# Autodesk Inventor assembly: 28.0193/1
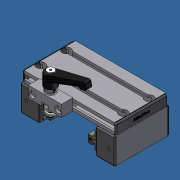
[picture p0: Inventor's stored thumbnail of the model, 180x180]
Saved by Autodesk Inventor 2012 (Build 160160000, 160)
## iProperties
Created: 2007-06
Part Number: 28.0193/1
Document SubType Name: Assembly
Designer: Andy Moles
Description: SLIDE LWN 32X45-90 WITH TOP CLAMP
Author: Andy Moles
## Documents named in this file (3)
- C:\Andys Backup Data\ANDY'S INVENTOR\INVENTOR LIBRARIES\PARTS LIBRARY\READY FOR USE MODULES LG\28.0193_1 SLIDE LWN 32X45-90 WITH TOP CLAMP.iam
- C:\Andys Backup Data\ANDY'S INVENTOR\INVENTOR LIBRARIES\PARTS LIBRARY\COMPONENTS LR\28.0270_9 SLIDE CLAMPING UNIT 5mm OFFSET..iam
- C:\Andys Backup Data\ANDY'S INVENTOR\INVENTOR LIBRARIES\PARTS LIBRARY\READY FOR USE MODULES LG\28.0193 SLIDE LWN 32X45-90.iam
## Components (2 placed, 2 different names)
1. 28.0270_9 SLIDE CLAMPING UNIT 5mm OFFSET.:1 [sub-assembly] — Mate:1, Mate:2, Flush:1
2. 28.0193 SLIDE LWN 32X45-90:1 [sub-assembly] — Mate:1, Mate:2, Flush:1
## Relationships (3: Mate 2, Flush 1)
- Mate:1: 28.0270_9 SLIDE CLAMPING UNIT 5mm OFFSET.:1 ↔ 28.0193 SLIDE LWN 32X45-90:1
- Mate:2: 28.0270_9 SLIDE CLAMPING UNIT 5mm OFFSET.:1 ↔ 28.0193 SLIDE LWN 32X45-90:1
- Flush:1: 28.0270_9 SLIDE CLAMPING UNIT 5mm OFFSET.:1 ↔ 28.0193 SLIDE LWN 32X45-90:1
